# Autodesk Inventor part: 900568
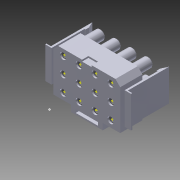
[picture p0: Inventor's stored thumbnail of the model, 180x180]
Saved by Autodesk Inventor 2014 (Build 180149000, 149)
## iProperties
Created: 2007-12
Part Number: 900568
Document SubType Name: Modeling
Designer: CF
Density: 1.06 g/cm^3
Categories: <MemberInstance><Categories><Category DisplayName="" Mnemonic="CABLEANDHARNESS" InternalName="e4a7e005-5e42-4d16-b293-125e7f0d0512"><Category DisplayName="" Mne
Mass: 5.15771 g
Surface Area: 57.5307 cm^2
Volume: 4.86577 cm^3
Material: ABS Plastic
Description: S65 CONTROL SWITCH CONNECTOR
Appearance: Cool White
GlobalPropertyList: <PropertyList/>
Component Category: Electrical
Author: CF
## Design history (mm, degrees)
sketch "Sketch1"
  geometry: L1 (-13.335, 8.89)-(13.335, 8.89); L2 (13.335, 8.89)-(13.335, -8.89); L3 (13.335, -8.89)-(-13.335, -8.89); L4 (-13.335, -8.89)-(-13.335, 8.89); L5 (-6.35, -8.89)-(6.35, -8.89); L6 (6.35, -8.89)-(6.35, -11.43); L7 (6.35, -11.43)-(-6.35, -11.43); L8 (-6.35, -11.43)-(-6.35, -8.89); L9 (-4.445, -9.525)-(4.445, -9.525); L10 (4.445, -9.525)-(4.445, -10.795); L11 (4.445, -10.795)-(-4.445, -10.795); L12 (-4.445, -10.795)-(-4.445, -9.525); C1 r 1.27 at (-9.525, 6.35); C2 r 1.905 at (-9.525, 6.35); 6 further points
  constraints: 24 end point, 6 parallel, 5 midpoint, 3 horizontal, 3 perpendicular, 3 vertical alignment, 2 centre point, 1 coincident, 1 horizontal alignment, 1 point on line
  dimensions: "Length" = 26.67 distance of L1.start L1.end; "Width" = 17.78 distance of L3.end L1.start; "Hole_Dia" = 2.54 diameter of C1; "Hole_Shell_Dia" = 3.81 diameter of C2; "Origin_Hole_Y" = 2.54 distance from line of L1 C1.centre; "Origin_Hole_X" = 3.81 distance from line of L4 C1.centre; "d18" = 1.27 distance of L9.end L10.end; "Tab_Space_Y" = 0.635 distance between parallel lines of L5 L9; "d20" = 0.635 distance between parallel lines of L7 L11 (= Tab_Space_Y); "Tab_Space_X" = 1.905 distance between parallel lines of L8 L12; "Bot_Tab_Length" = 12.7 distance of L6.end L7.end
extrude "Extrusion1" new body sketch "Sketch1" taper "d7" = 0 deg; distance "Block_Thck" = 8.89
extrude "Extrusion2" join sketch "Sketch1" taper "d9" = 0 deg; distance "Hole_Shell_Depth" = 6.35
extrude "Extrusion3" cut sketch "Sketch1" stored distance "d10" = 6.35; taper "d11" = 0 deg
pattern_linear "Rectangular Pattern1" dims "Occurence_Space_X" = 6.35, "Occurence_Space_Y" = 6.35
chamfer "Chamfer1" distance "Chamfer_Dis" = 1.905; stored, may be unused: second distance "d24" = 3.175, angle "d25" = 45 deg
sketch "Sketch2"
  geometry: L1 (-1.905, 8.89)-(1.905, 8.89); L2 (1.905, 8.89)-(1.905, 8.255); L3 (1.905, 8.255)-(-1.905, 8.255); L4 (-1.905, 8.255)-(-1.905, 8.89); L5 (-11.43, 8.89)-(11.43, 8.89) reference; 2 further points
  constraints: 8 end point, 2 parallel, 1 collinear, 1 horizontal, 1 midpoint, 1 perpendicular, 1 vertical alignment
  dimensions: "d26" = 3.81 distance of L2.end L3.end; "d27" = 0.635 distance between parallel lines of L1 L3
extrude "Extrusion4" cut sketch "Sketch2" distance "d28" = 2.54; taper "d29" = 0 deg
sketch "Sketch3"
  geometry: L1 (13.335, 0)-(13.335, 8.89) reference; L2 (13.335, 3.175)-(14.605, 3.175); L3 (14.605, 3.175)-(14.605, 5.715); L4 (14.605, 5.715)-(13.335, 5.715); L5 (13.335, 5.715)-(13.335, 3.175); L6 (14.605, 3.175)-(14.605, -4.826); L7 (14.605, -4.826)-(14.224, -4.826); L8 (14.224, -4.826)-(14.224, -6.185); L9 (14.224, -6.185)-(15.367, -8.636); L10 (15.367, -8.636)-(15.367, 7.874); L11 (15.367, 7.874)-(17.145, 7.874); L12 (17.145, 7.874)-(17.145, 8.382); L13 (17.145, 8.382)-(14.605, 8.382); L14 (14.605, 5.715)-(14.605, 8.382); L15 (6.35, 8.89)-(13.335, 8.89) reference; 3 further points
  constraints: 26 end point, 8 parallel, 3 perpendicular, 2 midpoint, 1 coincident, 1 horizontal, 1 point on line
  dimensions: "d30" = 1.27 distance of L2.start L2.end; "d31" = 2.54 distance of L2.end L3.end; "d32" = 0.508 distance between parallel lines of L13 L15; "d34" = 0.508 distance between parallel lines of L11 L13 (= d32); "d35" = 2.54 distance between parallel lines of L14 L12; "d36" = 0.762 distance between parallel lines of L14 L10; "d37" = 0.381 distance of L6.end L7.end; "d38" = 25 deg angle of L10 L9; "d39" = 16.51 distance of L9.end L10.end; "d40" = 3.81 distance from line of L9.end L7
extrude "Extrusion5" join sketch "Sketch3" stored distance "d41" = 1.905; taper "d42" = 0 deg
extrude "Extrusion6" join sketch "Sketch3" stored distance "d43" = 12.7; taper "d44" = 0 deg
mirror "Mirror1"
chamfer "Chamfer2" distance "d45" = 0.508; stored, may be unused: second distance "d46" = 3.175, angle "d47" = 45 deg
workplane "Work Plane1"
  workaxis "Work Axis1"
sketch "Sketch4"
  geometry: L1 (-9.398, 0)-(11.938, 0) reference; L2 (1.252, -0.635)-(-4.463, -0.635); L3 (-5.098, 0)-(1.252, 0); L4 (-6.35, -1.27)-(8.89, -1.27) reference; L5 (1.252, -0.635)-(2.159, -1.27); L6 (8.255, -1.27)-(8.255, -1.016); L7 (8.89, 1.27)-(8.89, -1.27) reference; L8 (1.252, 0)-(8.255, 0); L9 (-4.463, -0.381)-(1.332, -0.381); L10 (1.332, -0.381)-(2.239, -1.016); L11 (2.239, -1.016)-(8.255, -1.016); A1 r 0.635 centre (-4.463, 0) between (-5.098, 0) and (-4.463, -0.635); A2 r 0.381 centre (-4.463, 0) between (-4.844, 0) and (-4.463, -0.381); 1 further point
  constraints: 16 end point, 6 point on line, 4 point on circle, 2 centre point, 2 horizontal, 1 collinear, 1 parallel, 1 perpendicular, 1 tangent, 1 other
  dimensions: "d49" = 1.27 diameter of A1; "d51" = 145 deg angle of L2 L5; "d53" = 6.096 distance from line of L6 L5.end; "d54" = 0.635 distance between parallel lines of L6 L7; "d55" = 5.715 horizontal distance of A1.centre L2.start; "d56" = 0.254 distance between parallel lines of L11 L4; "d57" = 0.254 distance between parallel lines of L5 L10 (= d56); "d58" = 0.254 radial gap between concentric circles of A1 A2
revolve "Revolution1" sketch "Sketch4" stored, may be unused: angle "d59" = 90 deg
pattern_linear "Rectangular Pattern2" dims "d62" = 6.35 (= Occurence_Space_X), "d65" = 6.35 (= Occurence_Space_Y)
node "1"
node "2"
node "3"
node "4"
node "5"
node "6"
node "7"
node "8"
node "9"
node "10"
node "11"
node "12"
workpoint "Work Point13"
body "Solid1"
other parameters: "d48" = 90 deg
